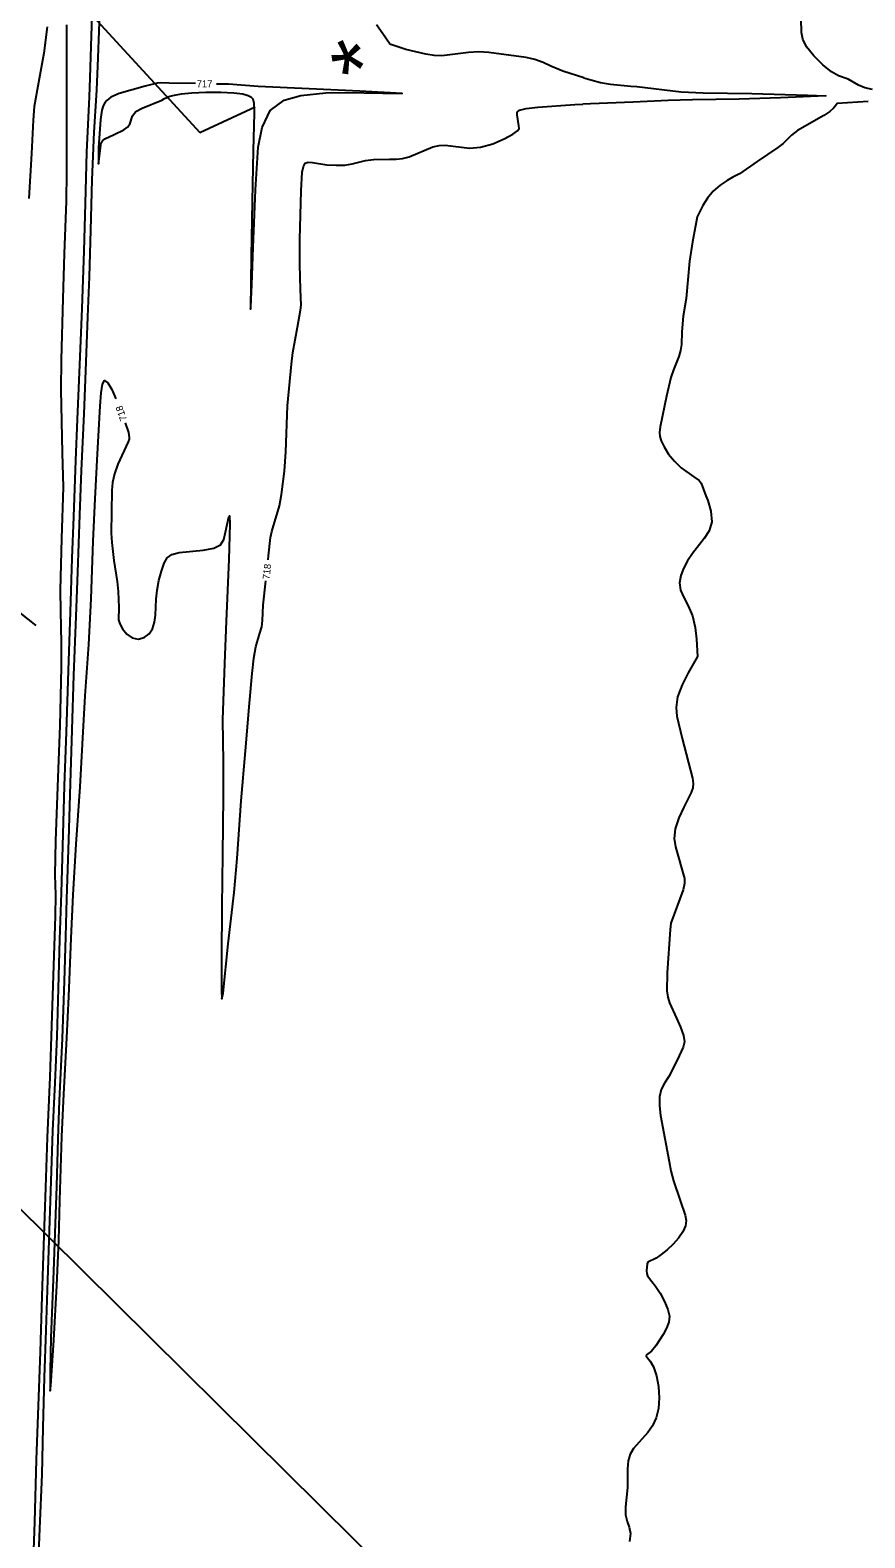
# Model space of a CAD drawing. Extents: x -310467766 to 17062430, y -322263100 to 8322522.
# Drawn here: x 1395694 to 1396171, y 572146 to 573008 of the extents above; entities that cross this region are included whole.
import ezdxf

# ---------------------------------------------------------------- set-up
doc = ezdxf.new("R2010")
doc.units = 0
for name, color, linetype in [('DT_X_Contour_Minor', 7, 'Continuous'), ('Level 19', 7, 'Continuous'), ('Level 40', 7, 'Continuous')]:
    doc.layers.add(name, color=color, linetype=linetype)

msp = doc.modelspace()

# ---------------------------------------------------------------- linework, layer by layer
at = {"layer": 'DT_X_Contour_Minor'}
for points in [[(1395697.98, 572122.43), (1395699.26, 572151.22), (1395700.43, 572182.12), (1395701.12, 572209.06), (1395701.85, 572237.54), (1395702.78, 572264.67), (1395703.76, 572293.14), (1395704.78, 572321.66), (1395705.68, 572349.76), (1395706.66, 572378.57), (1395707.84, 572406.04), (1395708.99, 572432.48), (1395709.89, 572460.08), (1395710.68, 572487.93), (1395711.54, 572514.75), (1395712.38, 572541.45), (1395713.36, 572575.79), (1395714.48, 572606.64), (1395715.64, 572641.8), (1395716.76, 572675.2), (1395717.71, 572705.98), (1395718.51, 572729.66), (1395719.68, 572761.79), (1395720.71, 572785.55), (1395722.09, 572816.63), (1395723.31, 572848.84), (1395724.42, 572881.73), (1395725.18, 572908.74), (1395726.1, 572938.1), (1395727.47, 572969.81), (1395727.97, 572980.61), (1395728.63, 573004.76), (1395729.62, 573033.14)], [(1395733.38, 573022.55), (1395732.28, 572992.01), (1395731.6, 572973.58), (1395730.02, 572949.61), (1395728.94, 572922.27), (1395728.18, 572893.53), (1395727.3, 572866.85), (1395726.49, 572843.96), (1395725.29, 572813.08), (1395724.22, 572788.56), (1395722.73, 572756.2), (1395721.75, 572730.86), (1395720.62, 572697.96), (1395719.77, 572672.77), (1395718.48, 572639.06), (1395717.41, 572607.97), (1395716.51, 572577.24), (1395715.57, 572545.05), (1395714.42, 572511.33), (1395713.77, 572489.54), (1395713.11, 572464.14), (1395712.02, 572431.34), (1395710.3, 572395.91), (1395709.44, 572374.06), (1395708.61, 572346.93), (1395707.79, 572320.07), (1395706.96, 572298.4), (1395705.52, 572260.29), (1395705.09, 572241.51), (1395705.1, 572229.95), (1395705.46, 572232.77), (1395707.15, 572258.87), (1395708.92, 572290.26), (1395710.11, 572315.87), (1395710.65, 572338.77), (1395711.78, 572375.36), (1395712.88, 572399.57), (1395714.53, 572431.79), (1395715.65, 572455.34), (1395717.1, 572488.72), (1395718.25, 572513.64), (1395719.88, 572542.46), (1395722.19, 572575.25), (1395723.61, 572599.62), (1395725.16, 572627.33), (1395727.14, 572656.6), (1395728.49, 572682.87), (1395729.6, 572715.68), (1395730.81, 572740.02), (1395732.15, 572765.61), (1395733.74, 572792.92), (1395734.27, 572800.51), (1395734.99, 572805.61), (1395736.16, 572807.64), (1395737.98, 572806.31), (1395740.26, 572802.41), (1395742.64, 572797.2)], [(1396174.94, 572973.97), (1396170.5, 572974.87), (1396166.88, 572976.44), (1396161.08, 572979.82), (1396155.43, 572981.86), (1396151.53, 572984.1), (1396146.51, 572988.14), (1396141.34, 572993.27), (1396137.22, 572998.42), (1396135.07, 573002.78), (1396134.37, 573006.65), (1396133.81, 573030.28)], [(1395703.29, 573009.77), (1395701.44, 572994.82), (1395698.45, 572978.02), (1395696.03, 572964.33), (1395695.42, 572956.46), (1395694.35, 572937.37), (1395692.98, 572911.63)], [(1395695.48, 572133.52), (1395696.32, 572155.07), (1395697.35, 572190.42), (1395698.36, 572221.46), (1395699.47, 572252.34), (1395700.52, 572284.14), (1395701.45, 572313.12), (1395702.54, 572346.26), (1395703.62, 572374.85), (1395705.01, 572409.32), (1395706.05, 572438.64), (1395707.03, 572467.43), (1395708.1, 572501.29), (1395708.25, 572513.5), (1395707.99, 572524.92), (1395708.29, 572544.43), (1395709.67, 572580.42), (1395710.71, 572610.44), (1395711.56, 572643.81), (1395711.49, 572657.59), (1395711.09, 572675.65), (1395711.07, 572687.77), (1395711.78, 572717.3), (1395712.69, 572746.66), (1395712.18, 572766.27), (1395711.27, 572802.23), (1395711.58, 572819.44), (1395712.59, 572854.48), (1395713.36, 572880.12), (1395714.46, 572910.23), (1395714.64, 572926.52), (1395714.69, 572955.25), (1395714.66, 572985.03), (1395714.6, 573010.91)], [(1396010.07, 572980.67), (1395998, 572984.42), (1395991.16, 572987.41), (1395986.7, 572989.39), (1395981.94, 572991.1), (1395977.11, 572992.2), (1395955.78, 572995.11), (1395949.91, 572995.45), (1395944.06, 572995.12), (1395928.84, 572993.3), (1395924.48, 572993.42), (1395919.64, 572994.12), (1395908.35, 572996.92), (1395899.76, 572999.73), (1395898.92, 573000.36), (1395895.14, 573005.76), (1395891.6, 573010.88)], [(1396010.07, 572980.6), (1396013.9, 572979.47), (1396019.6, 572978.06), (1396025.23, 572977.09), (1396036.94, 572975.96), (1396040.28, 572975.75), (1396065.6, 572972.74), (1396078.09, 572972.12), (1396105.99, 572971.62), (1396137.74, 572970.83), (1396148.24, 572970.46), (1396143.9, 572970.16), (1396122.44, 572969.28), (1396098.76, 572968.49), (1396071.99, 572968.16), (1396058.26, 572967.65), (1396038.15, 572966.72), (1396013.86, 572965.8), (1396009.51, 572965.66)], [(1395788.07, 572977.35), (1395772.99, 572977.62), (1395768.33, 572977.9), (1395766.22, 572977.62), (1395759.38, 572975.92), (1395744.48, 572971.62), (1395739.73, 572969.59), (1395737.39, 572967.74), (1395736.3, 572966.44), (1395735.37, 572964.61), (1395734.69, 572962.15), (1395733.92, 572956.76), (1395732.75, 572940.6), (1395732.73, 572931.47), (1395734.26, 572943.43), (1395734.94, 572944.71), (1395736.34, 572945.73), (1395741.64, 572948.3), (1395747.25, 572951.01), (1395749.27, 572952.45), (1395750.61, 572954.22), (1395752.19, 572958.97), (1395754.1, 572961.36), (1395757.64, 572963.38), (1395768.96, 572967.81), (1395770.46, 572968.91), (1395773.53, 572970.12), (1395776.18, 572970.81), (1395780.16, 572971.48), (1395786.02, 572972.04), (1395793.93, 572972.38), (1395802.52, 572972.44), (1395810.03, 572972.16), (1395815.12, 572971.51), (1395818.12, 572970.64), (1395819.82, 572969.73), (1395820.84, 572968.66), (1395821.39, 572966.09), (1395821.55, 572960.38), (1395821.1, 572939.16), (1395820.47, 572909.99), (1395819.86, 572878.74), (1395819.51, 572848.42), (1395819.67, 572849.47), (1395820.36, 572862.58), (1395821.08, 572883.57), (1395822.47, 572916.63), (1395824, 572940.98), (1395826.11, 572952.35), (1395830.85, 572961.99), (1395838.85, 572967.82), (1395848.29, 572970.54), (1395862.52, 572972), (1395873.18, 572972.21), (1395906.16, 572971.7), (1395882.01, 572972.98), (1395853.05, 572974.32), (1395823.89, 572975.79), (1395806.98, 572977.01), (1395800.06, 572977.14)], [(1395829.63, 572705.08), (1395829.88, 572707.4), (1395831.05, 572717.86), (1395831.81, 572721.37), (1395836.11, 572735.96), (1395837.31, 572742.44), (1395838.88, 572755.75), (1395839.69, 572766.83), (1395840.7, 572793.16), (1395842.89, 572817.03), (1395843.76, 572823.71), (1395846.36, 572838.19), (1395848.17, 572847.82), (1395848.42, 572850.74), (1395848.17, 572859.67), (1395847.74, 572874), (1395847.76, 572888.33), (1395848.44, 572916.12), (1395849.07, 572926.78), (1395849.74, 572929.99), (1395850.83, 572931.84), (1395852.48, 572932.45), (1395854.95, 572932.21), (1395863.2, 572930.99), (1395868.44, 572930.66), (1395873.44, 572930.8), (1395877.63, 572931.52), (1395885.28, 572933.44), (1395889.73, 572933.95), (1395898.89, 572934.17), (1395902.77, 572934.22), (1395906.4, 572934.59), (1395910.28, 572935.59), (1395923.68, 572941.19), (1395927.3, 572942.04), (1395930.68, 572942.09), (1395944.67, 572940.38), (1395951.04, 572940.97), (1395957.93, 572942.98), (1395964.42, 572945.78), (1395969.39, 572948.45), (1395972.09, 572950.33), (1395972.99, 572951.73), (1395972.92, 572953.22), (1395971.85, 572959.44), (1395971.9, 572961), (1395973.25, 572962.15), (1395977.03, 572963.06), (1395983.8, 572963.85), (1396004.8, 572965.37), (1396009.51, 572965.66)], [(1396172.43, 572967.21), (1396154.72, 572966.07), (1396153.79, 572964.65), (1396152.65, 572963.32), (1396150.57, 572961.47), (1396147.17, 572959.12), (1396132.09, 572950.49), (1396128.7, 572947.85), (1396123.83, 572943.15), (1396120.82, 572940.88), (1396109, 572932.89), (1396098.94, 572925.78), (1396095.15, 572923.83), (1396091.87, 572921.97), (1396087.92, 572919.33), (1396083.98, 572915.91), (1396080.64, 572911.84), (1396078.05, 572907.73), (1396074.8, 572901.12), (1396074.27, 572899.14), (1396072, 572886.93), (1396070.28, 572875.83), (1396068.52, 572854.48), (1396066.72, 572844.41), (1396065.92, 572835.53), (1396065.77, 572828.16), (1396065.29, 572824.8), (1396064.2, 572821.33), (1396061.15, 572813.66), (1396059.79, 572809.28), (1396057.31, 572798.69), (1396053.69, 572781.1), (1396053.2, 572777.81), (1396053.35, 572775.52), (1396054.23, 572773.09), (1396055.94, 572769.67), (1396058.46, 572765.59), (1396061.76, 572761.45), (1396065.68, 572757.77), (1396072.87, 572752.54), (1396075.96, 572750.36), (1396076.96, 572748.92), (1396079.79, 572741.71)], [(1395747.94, 572783.48), (1395749.8, 572777.89), (1395750.29, 572775.05), (1395750.18, 572774.12), (1395749.67, 572772.63), (1395743.8, 572759.81), (1395741.74, 572754.25), (1395740.64, 572749.39), (1395740.25, 572744.76), (1395739.99, 572720.41), (1395740.26, 572714.93), (1395741.51, 572704.71), (1395743.28, 572692.78), (1395743.95, 572686.98), (1395744.28, 572677.89), (1395744.08, 572670.71), (1395744.82, 572668.53), (1395746.46, 572665.62), (1395748.89, 572662.62), (1395751.95, 572660.45), (1395755.43, 572659.8), (1395758.86, 572660.63), (1395761.71, 572662.68), (1395763.6, 572665.68), (1395764.67, 572669.38), (1395765.18, 572673.52), (1395765.64, 572682.62), (1395766.17, 572687.74), (1395767.23, 572693.25), (1395768.67, 572698.61), (1395770.28, 572703.11), (1395772.02, 572706.25), (1395774.59, 572708.19), (1395778.86, 572709.3), (1395792.43, 572710.57)], [(1396079.79, 572741.71), (1396080.82, 572738.99), (1396082.54, 572732.85), (1396083.05, 572726.77), (1396081.63, 572721.61), (1396078.8, 572717.19), (1396072.14, 572708.8), (1396069.28, 572704.49), (1396066.95, 572700.21), (1396065.33, 572696.04), (1396064.67, 572691.94), (1396065.23, 572687.81), (1396067.12, 572683.52), (1396069.67, 572678.73), (1396072.05, 572673.05), (1396073.59, 572666.36), (1396074.4, 572659.7), (1396074.92, 572649.83), (1396069.57, 572640.49), (1396066.15, 572633.7), (1396063.57, 572626.77), (1396062.7, 572620.75), (1396063.14, 572615.66), (1396066.21, 572602.94), (1396072.04, 572580.28), (1396072.55, 572577.18), (1396072.28, 572574.78), (1396071.39, 572572.04), (1396067.19, 572563.76), (1396064.24, 572557.61), (1396062.11, 572551.36), (1396061.61, 572545.8), (1396062.36, 572540.95), (1396067.59, 572522.97), (1396067.6, 572520.08), (1396066.78, 572516.47), (1396059.77, 572497.38), (1396059.25, 572493.65), (1396057.65, 572468.92), (1396057.47, 572458.74), (1396057.93, 572455.06), (1396058.92, 572451.75), (1396062.92, 572443.09), (1396065.31, 572437.81), (1396067.02, 572433.06), (1396067.49, 572429.48), (1396066.83, 572426.5), (1396063.32, 572418.99), (1396058.51, 572409.77), (1396056.16, 572405.94), (1396054.26, 572402.29), (1396053.18, 572398.09), (1396053.15, 572392.9), (1396053.83, 572387.41), (1396058.67, 572361.15), (1396059.75, 572355.76), (1396061.21, 572349.99), (1396064.99, 572338.81), (1396067.97, 572330.45), (1396068.47, 572327.35), (1396068.02, 572324.3), (1396066.52, 572320.92), (1396064.12, 572317.34), (1396061.07, 572313.8), (1396057.65, 572310.56), (1396054.24, 572307.84), (1396051.24, 572305.88), (1396046.54, 572303.54), (1396046.1, 572302.61), (1396045.89, 572298.53), (1396045.98, 572297.1), (1396046.39, 572295.73), (1396048.83, 572292.55), (1396050.92, 572289.78), (1396053.52, 572285.74), (1396056.11, 572281.02), (1396058.05, 572276.43), (1396058.85, 572272.58), (1396058.55, 572269.2), (1396057.3, 572265.84), (1396055.34, 572262.18), (1396051.08, 572255.67), (1396048.63, 572252.66), (1396045.72, 572250.58), (1396045.54, 572249.77), (1396047.92, 572246.85), (1396049.74, 572243.6), (1396051.42, 572238.56), (1396052.64, 572232.37), (1396053.12, 572225.89), (1396052.62, 572219.86), (1396051.24, 572214.51), (1396049.13, 572209.93), (1396046.47, 572206.14), (1396038.28, 572196.97), (1396036.4, 572193.7), (1396035.26, 572189.89), (1396034.89, 572185.36), (1396034.85, 572174.72), (1396033.85, 572163.66), (1396033.88, 572158.98)], [(1395792.43, 572710.57), (1395798.57, 572711.69), (1395802.34, 572713.72), (1395804.25, 572716.79), (1395805.29, 572720.95), (1395807.08, 572729.72), (1395807.63, 572730.2), (1395807.74, 572725.69), (1395807.07, 572705.27), (1395805.71, 572669.95), (1395804.72, 572645.76), (1395803.61, 572613.51), (1395803.92, 572589.66), (1395803.99, 572569.71), (1395803.58, 572536.67), (1395803.23, 572506.8), (1395803.03, 572478.16), (1395802.9, 572458.65), (1395803.16, 572454.06), (1395803.83, 572457.38), (1395806.76, 572485.47), (1395810.3, 572514.87), (1395811.92, 572534.28), (1395814.2, 572567.38), (1395816.65, 572595.97), (1395819.02, 572623.05), (1395820.5, 572640.12), (1395821.53, 572648.88), (1395822.64, 572655.31), (1395824.7, 572662.65), (1395825.96, 572666.81), (1395826.31, 572670.36), (1395826.85, 572679.18), (1395828.35, 572693.15)], [(1396033.88, 572158.98), (1396034.77, 572155.27), (1396035.95, 572151.97), (1396036.57, 572148.32), (1396036.04, 572143.79)]]:
    msp.add_lwpolyline(points, dxfattribs=at)
at = {"layer": 'Level 40'}
for p, q in [((1395710.67, 573036.6), (1395790.68, 572949.37)), ((1395790.68, 572949.37), (1395822.22, 572964.08)), ((1395697.04, 572667.55), (1395517.5, 572808.75)), ((1395684.84, 572337.08), (1396318.06, 571710.25))]:
    msp.add_line(p, q, dxfattribs=at)

# ---------------------------------------------------------------- texts
at = {"layer": 'Level 19'}
for s, rotation, p in [('717', 358.96952, (1395788.77, 572975.34)), ('718', 109.74426, (1395749.09, 572785.26)), ('718', 83.86956, (1395830.42, 572693.69))]:
    msp.add_text(s, height=4, rotation=rotation, dxfattribs=at).set_placement(p)
at = {"layer": 'Level 40'}
msp.add_text('*', height=37.5, rotation=25, dxfattribs=at).set_placement((1395877.76, 572963.45))

doc.saveas('drawing.dxf')
